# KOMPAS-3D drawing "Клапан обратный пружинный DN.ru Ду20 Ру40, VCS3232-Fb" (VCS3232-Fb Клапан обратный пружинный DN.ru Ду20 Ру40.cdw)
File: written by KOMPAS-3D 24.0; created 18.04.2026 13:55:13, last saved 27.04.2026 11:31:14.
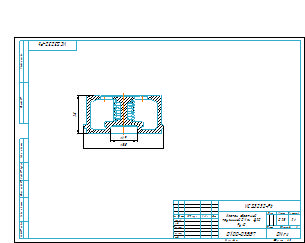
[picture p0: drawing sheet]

Document properties: c3d_UniqueCompID: 071bd168-1a06-425c-849c-e99e84a96128; Наименование: Деталь; Автор: 712; Класс точности: c; Знак неуказанной шероховатости: Шероховатость не задана; Рассекать на разрезах: Да; c3d_UniqueCompID: 071bd168-1a06-425c-849c-e99e84a96128; Наименование: Деталь; Автор: 712; Класс точности: c; Знак неуказанной шероховатости: Шероховатость не задана; Рассекать на разрезах: Да; c3d_UniqueCompID: 071bd168-1a06-425c-849c-e99e84a96128; Наименование: Деталь; Автор: 712; Класс точности: c; Знак неуказанной шероховатости: Шероховатость не задана; Рассекать на разрезах: Да; Автор: 712; Форматы листов документа: A3; Полное имя файла: VCS3232-Fb Клапан обратный пружинный DN.ru Ду20 Ру40.m3d; Масса: 0.25; Наименование: Клапан обратный пружинный DN.ru Ду20 Ру40; Количество листов документа: 1; Примечание: D100-03887

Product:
- Component: Пружина 1086-0796 ГОСТ 18793-80  | qty 1  | additional columns: 3953604318-4147491677-0; Деталь; Пользователь Windows; c; Шероховатость не задана; Да; Сталь 10  ГОСТ 1050-88; source file: Деталь.m3d
- Body: Тело 1  | qty 1
    Масса: 0.217807
- Part/product: Клапан обратный пружинный DN.ru Ду20 Ру40  | designation VCS3232-Fb
    Масса: 0.25
    Раздел спецификации: Прочие изделия
    Примечание: D100-03887
    additional columns: 071bd168-1a06-425c-849c-e99e84a96128; Деталь; 712; c; Шероховатость не задана; Да

Views: Вид 1, Местный разрез 1, Спереди
Referenced files in C:\Users\712\Desktop\Новая папка (4)\: VCS3232-Fb Клапан обратный пружинный DN.ru Ду15 Ру40.m3d, VCS3232-Fb Клапан обратный пружинный DN.ru Ду20 Ру40.m3d, VCS3232-Fb Клапан обратный пружинный DN.ru Ду15 Ру40.cdw
Referenced files in C:\Users\Пупс\Desktop\Работа\Работа\проверка\VCS3232-Fb WDVF Ду15-200 Ру40-25 Клапан обратный пружинный DN.ru\Ду20\: VCS3232-Fb Клапан обратный пружинный DN.ru Ду20 Ру40.m3d
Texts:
  Линейный размер
  VCS3232-Fb
  Клапан обратный
  пружинный DN.ru Ду20
  Ру40
  Клапан обратный пружинный DN.ru Ду20 Ру40
  VCS3232-Fb Клапан обратный пружинный DN.ru Ду20 Ру40
Dimensions and other numbers on the sheet: 0; 3; 2; 4; 19; 28; 58; 7; 2:1; 1; 0,25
